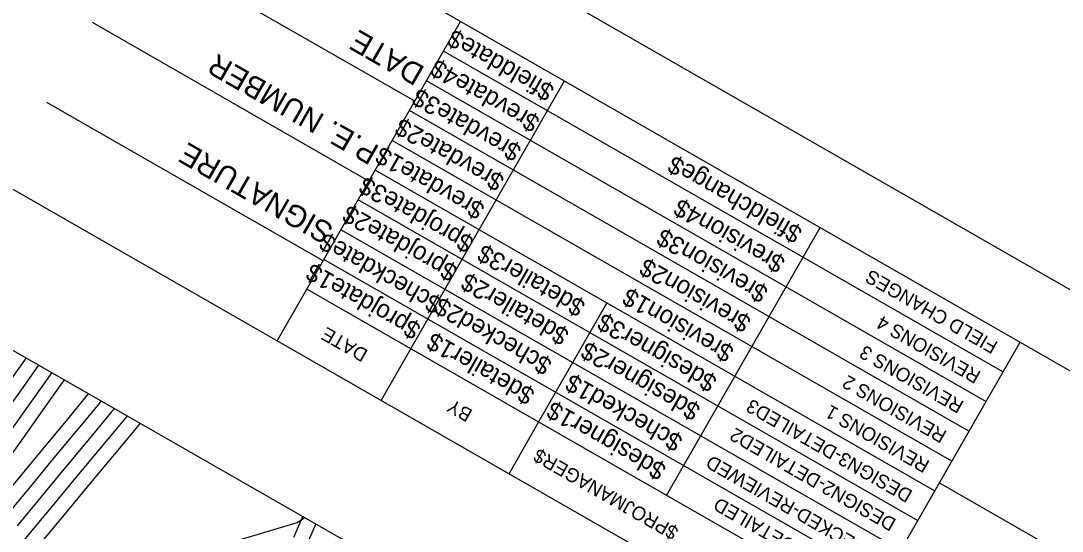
# Model space of a CAD drawing. Extents: x 1160447 to 1162032, y 616022 to 618272.
# Drawn here: x 1160997.8 to 1161139.1, y 616845.1 to 616914.4 of the extents above; entities that cross this region are included whole.
import ezdxf

# ---------------------------------------------------------------- set-up
doc = ezdxf.new("R2010")
doc.units = 0
for name, color, linetype in [('BORDER', 7, 'Continuous'), ('D_Contours_Major', 7, 'Continuous'), ('D_Contours_Minor', 7, 'Continuous'), ('PLOT BOUNDARY', 7, 'Continuous'), ('Plot Boundary_1', 7, 'Continuous')]:
    doc.layers.add(name, color=color, linetype=linetype)

msp = doc.modelspace()

# ---------------------------------------------------------------- linework, layer by layer
at = {"layer": 'BORDER'}
for p, q in [((1161303.72, 616715.44), (1160848.31, 616976.65)), ((1161051.29, 616903.46), (1161013.78, 616924.97)), ((1161045.07, 616892.62), (1161007.56, 616914.13)), ((1161032.63, 616870.93), (1161057.51, 616914.3)), ((1161038.85, 616881.77), (1161001.35, 616903.29)), ((1161108.53, 616827.39), (1161133.41, 616870.77)), ((1161274.24, 616764.57), (1161122.44, 616851.64))]:
    msp.add_line(p, q, dxfattribs=at)
msp.add_lwpolyline([(1160475.14, 616326.08), (1160873.19, 617020.03), (1161328.59, 616758.81), (1160930.55, 616064.86)], close=True, dxfattribs=at)
for points in [[(1161131.08, 616866.74), (1161055.19, 616910.27)], [(1161046.73, 616862.85), (1161071.6, 616906.22)], [(1161128.76, 616862.7), (1161052.88, 616906.22)], [(1161126.44, 616858.65), (1161050.56, 616902.18)], [(1161124.13, 616854.61), (1161048.24, 616898.14)], [(1161121.81, 616850.57), (1161045.92, 616894.1)], [(1161119.49, 616846.53), (1161043.6, 616890.06)], [(1161041.29, 616886.02), (1161117.17, 616842.49)], [(1161085.44, 616849.95), (1161106.3, 616886.31)], [(1161114.86, 616838.45), (1161038.97, 616881.98)], [(1161050.74, 616869.85), (1161036.65, 616877.93)], [(1161112.54, 616834.41), (1161039.71, 616876.18)], [(1161068.09, 616859.9), (1161077.36, 616876.06)], [(1161064.08, 616852.89), (1161068.09, 616859.9)]]:
    msp.add_lwpolyline(points, dxfattribs=at)
at = {"layer": 'D_Contours_Major'}
for points in [[(1161007.04, 616863.78), (1161006.95, 616863.68), (1161003.75, 616859.82), (1161000.56, 616855.97), (1160997.37, 616852.12), (1160994.18, 616848.27), (1160990.99, 616844.41), (1160987.8, 616840.56), (1160984.61, 616836.7), (1160981.42, 616832.84), (1160978.24, 616828.98), (1160975.15, 616825.24), (1160977.96, 616829.2), (1160980.85, 616833.28), (1160983.75, 616837.36), (1160986.65, 616841.44), (1160989.54, 616845.52), (1160992.43, 616849.6), (1160995.32, 616853.69), (1160998.21, 616857.77), (1161001.1, 616861.86), (1161003.78, 616865.65)], [(1160975.33, 616809.76), (1160976.62, 616811.32), (1160979.81, 616815.18), (1160982.99, 616819.04), (1160986.17, 616822.9), (1160989.36, 616826.76), (1160992.55, 616830.62), (1160995.73, 616834.47), (1160998.92, 616838.33), (1161001.83, 616841.84), (1161002.43, 616841.94), (1161006.15, 616842.54), (1161010.36, 616842.17), (1161015.21, 616841.72), (1161018.4, 616842.3), (1161024.16, 616843.33), (1161025.22, 616843.37), (1161027.33, 616843.88), (1161031.24, 616845.06), (1161035.35, 616846.28), (1161036.36, 616846.96)], [(1161037.88, 616846.09), (1161036.7, 616843.4)]]:
    msp.add_lwpolyline(points, dxfattribs=at)
at = {"layer": 'D_Contours_Minor'}
for points in [[(1160998.56, 616868.64), (1160996.34, 616865.51)], [(1160995.04, 616860.21), (1160997.93, 616864.29), (1161000.3, 616867.65)], [(1161002.04, 616866.65), (1160999.51, 616863.07), (1160996.62, 616858.99)], [(1160995.76, 616847.05), (1160998.96, 616850.9), (1161002.15, 616854.76), (1161005.34, 616858.61), (1161008.54, 616862.46), (1161008.8, 616862.77)], [(1161010.55, 616861.76), (1161010.12, 616861.24), (1161006.93, 616857.39), (1161003.74, 616853.54), (1161000.54, 616849.69), (1160997.35, 616845.83)], [(1160995.75, 616840.76), (1160998.94, 616844.62), (1161002.13, 616848.47), (1161005.32, 616852.32), (1161008.52, 616856.17), (1161011.71, 616860.03), (1161012.31, 616860.75)], [(1160973.79, 616811.03), (1160975.04, 616812.54), (1160978.22, 616816.4), (1160981.4, 616820.26), (1160984.59, 616824.12), (1160987.77, 616827.98), (1160990.96, 616831.83), (1160994.15, 616835.69), (1160997.34, 616839.55), (1161000.53, 616843.4), (1161003.72, 616847.25), (1161006.91, 616851.11), (1161010.1, 616854.96), (1161013.3, 616858.81), (1161014.07, 616859.74)], [(1161036.08, 616847.12), (1161035.95, 616846.81), (1161034.82, 616844.23)]]:
    msp.add_lwpolyline(points, dxfattribs=at)
at = {"layer": 'PLOT BOUNDARY'}
msp.add_lwpolyline([(1160923.68, 616022.15), (1161346.6, 616759.47), (1160869.52, 617033.12), (1160446.59, 616295.81)], close=True, dxfattribs=at)
at = {"layer": 'Plot Boundary_1'}
msp.add_lwpolyline([(1160500.57, 616331.28), (1160855.78, 616950.54), (1161275.71, 616709.67), (1160920.5, 616090.41)], close=True, dxfattribs=at)

# ---------------------------------------------------------------- texts
at = {"layer": 'BORDER'}
for s, height, p in [('DATE', 2.953, (1161052.8, 616908.02)), ('$fielddate$', 2.4227, (1161070.4, 616905.41)), ('P.E. NUMBER', 2.9528, (1161046.63, 616897.26)), ('$revdate4$', 2.423, (1161068.42, 616901.17)), ('$revdate3$', 2.423, (1161065.93, 616897.23)), ('$revdate2$', 2.423, (1161063.61, 616893.19)), ('SIGNATURE', 2.953, (1161040.46, 616886.5)), ('$revdate1$', 2.423, (1161060.95, 616889.34)), ('$fieldchange$', 2.4227, (1161104.03, 616886.11)), ('$projdate3$', 2.4227, (1161059.49, 616884.81)), ('$revision4$', 2.4227, (1161101.72, 616882.07)), ('$projdate2$', 2.4227, (1161057.26, 616880.93)), ('$checkdate$', 2.4227, (1161055.2, 616876.53)), ('$revision3$', 2.4227, (1161099.4, 616878.03)), ('$detailer3$', 2.4227, (1161074.61, 616876.14)), ('$projdate1$', 2.4227, (1161052.29, 616873.05)), ('$revision2$', 2.4227, (1161097.08, 616873.99)), ('$detailer2$', 2.4227, (1161072.39, 616872.26)), ('FIELD CHANGES', 1.8637, (1161130.55, 616870.69)), ('$revision1$', 2.4227, (1161094.76, 616869.95)), ('$checked2$', 2.423, (1161070.07, 616868.22)), ('$designer3$', 2.4227, (1161092.45, 616865.91)), ('REVISIONS 4', 1.8637, (1161128.23, 616866.65)), ('DATE', 1.857, (1161045.08, 616869.58)), ('$detailer1$', 2.4227, (1161067.75, 616864.18)), ('$designer2$', 2.4227, (1161090.22, 616862.03)), ('REVISIONS 3', 1.8637, (1161125.92, 616862.61)), ('$checked1$', 2.423, (1161087.81, 616857.83)), ('REVISIONS 2', 1.8637, (1161123.6, 616858.57)), ('DESIGN3-DETAILED3', 1.8637, (1161118.96, 616850.49)), ('BY', 1.857, (1161059.27, 616861.44)), ('$designer1$', 2.4227, (1161085.58, 616853.95)), ('REVISIONS 1', 1.8637, (1161121.28, 616854.53)), ('DESIGN2-DETAILED2', 1.8637, (1161116.74, 616846.61)), ('$PROJMANAGER$', 1.8637, (1161087.2, 616845.42)), ('CHECKED-REVIEWED', 1.8637, (1161114.33, 616842.4)), ('DESIGN-DETAILED', 1.8637, (1161112.1, 616838.53))]:
    msp.add_text(s, height=height, rotation=150.1613, dxfattribs=at).set_placement(p)

doc.saveas('drawing.dxf')
